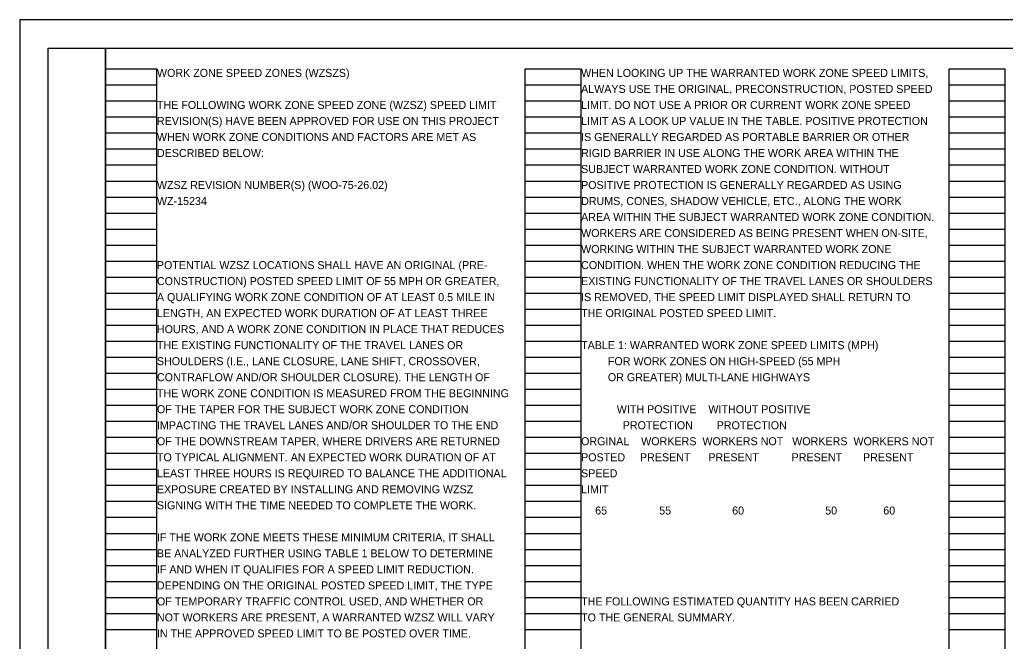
# Model space of a CAD drawing. Extents: x 0 to 34, y 0 to 22.
# Drawn here: x 0 to 17.24, y 11.13 to 22 of the extents above; entities that cross this region are included whole.
import ezdxf

# ---------------------------------------------------------------- set-up
doc = ezdxf.new("R2010")
doc.units = 0
for name, color, linetype in [('SH_Border', 7, 'Continuous'), ('SH_Cut_Line', 7, 'Continuous'), ('SH_Data', 7, 'Continuous'), ('SH_Text', 7, 'Continuous')]:
    doc.layers.add(name, color=color, linetype=linetype)

msp = doc.modelspace()

# ---------------------------------------------------------------- linework, layer by layer
at = {"layer": 'SH_Border'}
for points in [[(0.5, 21.5), (1.5, 21.5), (1.5, 0.5), (0.5, 0.5)], [(1.5, 21.5), (33.5, 21.5), (33.5, 0.5), (1.5, 0.5)]]:
    msp.add_lwpolyline(points, close=True, dxfattribs=at)
at = {"layer": 'SH_Cut_Line'}
msp.add_lwpolyline([(0, 0), (34, 0), (34, 22), (0, 22)], close=True, dxfattribs=at)
at = {"layer": 'SH_Data'}
for p, q in [((1.5, 0.98), (1.5, 21.14)), ((1.5, 21.14), (2.4, 21.14)), ((2.4, 0.98), (2.4, 21.14)), ((8.84, 0.98), (8.84, 21.14)), ((8.84, 21.14), (9.82, 21.14)), ((9.82, 0.98), (9.82, 21.14)), ((16.26, 0.98), (16.26, 21.14)), ((16.26, 21.14), (17.24, 21.14)), ((17.24, 0.98), (17.24, 21.14)), ((1.5, 20.86), (2.4, 20.86)), ((8.84, 20.86), (9.82, 20.86)), ((16.26, 20.86), (17.24, 20.86)), ((1.5, 20.58), (2.4, 20.58)), ((8.84, 20.58), (9.82, 20.58)), ((16.26, 20.58), (17.24, 20.58)), ((1.5, 20.3), (2.4, 20.3)), ((8.84, 20.3), (9.82, 20.3)), ((16.26, 20.3), (17.24, 20.3)), ((1.5, 20.02), (2.4, 20.02)), ((8.84, 20.02), (9.82, 20.02)), ((16.26, 20.02), (17.24, 20.02)), ((1.5, 19.74), (2.4, 19.74)), ((8.84, 19.74), (9.82, 19.74)), ((16.26, 19.74), (17.24, 19.74)), ((1.5, 19.46), (2.4, 19.46)), ((8.84, 19.46), (9.82, 19.46)), ((16.26, 19.46), (17.24, 19.46)), ((1.5, 19.18), (2.4, 19.18)), ((8.84, 19.18), (9.82, 19.18)), ((16.26, 19.18), (17.24, 19.18)), ((1.5, 18.9), (2.4, 18.9)), ((8.84, 18.9), (9.82, 18.9)), ((16.26, 18.9), (17.24, 18.9)), ((1.5, 18.62), (2.4, 18.62)), ((8.84, 18.62), (9.82, 18.62)), ((16.26, 18.62), (17.24, 18.62)), ((1.5, 18.34), (2.4, 18.34)), ((8.84, 18.34), (9.82, 18.34)), ((16.26, 18.34), (17.24, 18.34)), ((1.5, 18.06), (2.4, 18.06)), ((8.84, 18.06), (9.82, 18.06)), ((16.26, 18.06), (17.24, 18.06)), ((1.5, 17.78), (2.4, 17.78)), ((8.84, 17.78), (9.82, 17.78)), ((16.26, 17.78), (17.24, 17.78)), ((1.5, 17.5), (2.4, 17.5)), ((8.84, 17.5), (9.82, 17.5)), ((16.26, 17.5), (17.24, 17.5)), ((1.5, 17.22), (2.4, 17.22)), ((8.84, 17.22), (9.82, 17.22)), ((16.26, 17.22), (17.24, 17.22)), ((1.5, 16.94), (2.4, 16.94)), ((8.84, 16.94), (9.82, 16.94)), ((16.26, 16.94), (17.24, 16.94)), ((1.5, 16.66), (2.4, 16.66)), ((8.84, 16.66), (9.82, 16.66)), ((16.26, 16.66), (17.24, 16.66)), ((1.5, 16.38), (2.4, 16.38)), ((8.84, 16.38), (9.82, 16.38)), ((16.26, 16.38), (17.24, 16.38)), ((1.5, 16.1), (2.4, 16.1)), ((8.84, 16.1), (9.82, 16.1)), ((16.26, 16.1), (17.24, 16.1)), ((1.5, 15.82), (2.4, 15.82)), ((8.84, 15.82), (9.82, 15.82)), ((16.26, 15.82), (17.24, 15.82)), ((1.5, 15.54), (2.4, 15.54)), ((8.84, 15.54), (9.82, 15.54)), ((16.26, 15.54), (17.24, 15.54)), ((1.5, 15.26), (2.4, 15.26)), ((8.84, 15.26), (9.82, 15.26)), ((16.26, 15.26), (17.24, 15.26)), ((1.5, 14.98), (2.4, 14.98)), ((8.84, 14.98), (9.82, 14.98)), ((16.26, 14.98), (17.24, 14.98)), ((1.5, 14.7), (2.4, 14.7)), ((8.84, 14.7), (9.82, 14.7)), ((16.26, 14.7), (17.24, 14.7)), ((1.5, 14.42), (2.4, 14.42)), ((8.84, 14.42), (9.82, 14.42)), ((16.26, 14.42), (17.24, 14.42)), ((1.5, 14.14), (2.4, 14.14)), ((8.84, 14.14), (9.82, 14.14)), ((16.26, 14.14), (17.24, 14.14)), ((1.5, 13.86), (2.4, 13.86)), ((8.84, 13.86), (9.82, 13.86)), ((16.26, 13.86), (17.24, 13.86)), ((1.5, 13.58), (2.4, 13.58)), ((8.84, 13.58), (9.82, 13.58)), ((16.26, 13.58), (17.24, 13.58)), ((1.5, 13.3), (2.4, 13.3)), ((8.84, 13.3), (9.82, 13.3)), ((16.26, 13.3), (17.24, 13.3)), ((1.5, 13.02), (2.4, 13.02)), ((8.84, 13.02), (9.82, 13.02)), ((16.26, 13.02), (17.24, 13.02)), ((1.5, 12.74), (2.4, 12.74)), ((8.84, 12.74), (9.82, 12.74)), ((16.26, 12.74), (17.24, 12.74)), ((1.5, 12.46), (2.4, 12.46)), ((8.84, 12.46), (9.82, 12.46)), ((16.26, 12.46), (17.24, 12.46)), ((1.5, 12.18), (2.4, 12.18)), ((8.84, 12.18), (9.82, 12.18)), ((16.26, 12.18), (17.24, 12.18)), ((1.5, 11.9), (2.4, 11.9)), ((8.84, 11.9), (9.82, 11.9)), ((16.26, 11.9), (17.24, 11.9)), ((1.5, 11.62), (2.4, 11.62)), ((8.84, 11.62), (9.82, 11.62)), ((16.26, 11.62), (17.24, 11.62)), ((1.5, 11.34), (2.4, 11.34)), ((8.84, 11.34), (9.82, 11.34)), ((16.26, 11.34), (17.24, 11.34))]:
    msp.add_line(p, q, dxfattribs=at)

# ---------------------------------------------------------------- texts
at = {"layer": 'SH_Text'}
for s, p in [('WORK ZONE SPEED ZONES (WZSZS)', (2.4, 21)), ('WHEN LOOKING UP THE WARRANTED WORK ZONE SPEED LIMITS,', (9.82, 21)), ('ALWAYS USE THE ORIGINAL, PRECONSTRUCTION, POSTED SPEED', (9.82, 20.72)), ('THE FOLLOWING WORK ZONE SPEED ZONE (WZSZ) SPEED LIMIT', (2.4, 20.44)), ('LIMIT. DO NOT USE A PRIOR OR CURRENT WORK ZONE SPEED', (9.82, 20.44)), ('REVISION(S) HAVE BEEN APPROVED FOR USE ON THIS PROJECT', (2.4, 20.16)), ('LIMIT AS A LOOK UP VALUE IN THE TABLE. POSITIVE PROTECTION', (9.82, 20.16)), ('WHEN WORK ZONE CONDITIONS AND FACTORS ARE MET AS', (2.4, 19.88)), ('IS GENERALLY REGARDED AS PORTABLE BARRIER OR OTHER', (9.82, 19.88)), ('DESCRIBED BELOW:', (2.4, 19.6)), ('RIGID BARRIER IN USE ALONG THE WORK AREA WITHIN THE', (9.82, 19.6)), ('SUBJECT WARRANTED WORK ZONE CONDITION. WITHOUT', (9.82, 19.32)), ('WZSZ REVISION NUMBER(S) (WOO-75-26.02)', (2.4, 19.04)), ('POSITIVE PROTECTION IS GENERALLY REGARDED AS USING', (9.82, 19.04)), ('WZ-15234', (2.4, 18.76)), ('DRUMS, CONES, SHADOW VEHICLE, ETC., ALONG THE WORK', (9.82, 18.76)), ('AREA WITHIN THE SUBJECT WARRANTED WORK ZONE CONDITION.', (9.82, 18.48)), ('WORKERS ARE CONSIDERED AS BEING PRESENT WHEN ON-SITE,', (9.82, 18.2)), ('WORKING WITHIN THE SUBJECT WARRANTED WORK ZONE', (9.82, 17.92)), ('POTENTIAL WZSZ LOCATIONS SHALL HAVE AN ORIGINAL (PRE-', (2.4, 17.64)), ('CONDITION. WHEN THE WORK ZONE CONDITION REDUCING THE', (9.82, 17.64)), ('CONSTRUCTION) POSTED SPEED LIMIT OF 55 MPH OR GREATER,', (2.4, 17.36)), ('EXISTING FUNCTIONALITY OF THE TRAVEL LANES OR SHOULDERS', (9.82, 17.36)), ('A QUALIFYING WORK ZONE CONDITION OF AT LEAST 0.5 MILE IN', (2.4, 17.08)), ('IS REMOVED, THE SPEED LIMIT DISPLAYED SHALL RETURN TO', (9.82, 17.08)), ('LENGTH, AN EXPECTED WORK DURATION OF AT LEAST THREE', (2.4, 16.8)), ('THE ORIGINAL POSTED SPEED LIMIT.', (9.82, 16.8)), ('HOURS, AND A WORK ZONE CONDITION IN PLACE THAT REDUCES', (2.4, 16.52)), ('THE EXISTING FUNCTIONALITY OF THE TRAVEL LANES OR', (2.4, 16.24)), ('TABLE 1: WARRANTED WORK ZONE SPEED LIMITS (MPH)', (9.82, 16.24)), ('SHOULDERS (I.E., LANE CLOSURE, LANE SHIFT, CROSSOVER,', (2.4, 15.96)), ('         FOR WORK ZONES ON HIGH-SPEED (55 MPH', (9.82, 15.96)), ('CONTRAFLOW AND/OR SHOULDER CLOSURE). THE LENGTH OF', (2.4, 15.68)), ('         OR GREATER) MULTI-LANE HIGHWAYS', (9.82, 15.68)), ('THE WORK ZONE CONDITION IS MEASURED FROM THE BEGINNING', (2.4, 15.4)), ('OF THE TAPER FOR THE SUBJECT WORK ZONE CONDITION', (2.4, 15.12)), ('            WITH POSITIVE    WITHOUT POSITIVE', (9.82, 15.12)), ('IMPACTING THE TRAVEL LANES AND/OR SHOULDER TO THE END', (2.4, 14.84)), ('              PROTECTION        PROTECTION', (9.82, 14.84)), ('OF THE DOWNSTREAM TAPER, WHERE DRIVERS ARE RETURNED', (2.4, 14.56)), ('ORGINAL    WORKERS  WORKERS NOT   WORKERS  WORKERS NOT', (9.82, 14.56)), ('TO TYPICAL ALIGNMENT. AN EXPECTED WORK DURATION OF AT', (2.4, 14.28)), ('POSTED     PRESENT      PRESENT           PRESENT       PRESENT', (9.82, 14.28)), ('LEAST THREE HOURS IS REQUIRED TO BALANCE THE ADDITIONAL', (2.4, 14)), ('SPEED', (9.82, 14)), ('EXPOSURE CREATED BY INSTALLING AND REMOVING WZSZ', (2.4, 13.72)), ('LIMIT', (9.82, 13.72)), ('SIGNING WITH THE TIME NEEDED TO COMPLETE THE WORK.', (2.4, 13.44)), (' 65        ', (10.014, 13.349)), (' 55      ', (11.134, 13.349)), ('    60              ', (12.254, 13.349)), ('   50 ', (13.934, 13.349)), (' 60', (15.054, 13.349)), ('IF THE WORK ZONE MEETS THESE MINIMUM CRITERIA, IT SHALL', (2.4, 12.88)), ('BE ANALYZED FURTHER USING TABLE 1 BELOW TO DETERMINE', (2.4, 12.6)), ('IF AND WHEN IT QUALIFIES FOR A SPEED LIMIT REDUCTION.', (2.4, 12.32)), ('DEPENDING ON THE ORIGINAL POSTED SPEED LIMIT, THE TYPE', (2.4, 12.04)), ('OF TEMPORARY TRAFFIC CONTROL USED, AND WHETHER OR', (2.4, 11.76)), ('THE FOLLOWING ESTIMATED QUANTITY HAS BEEN CARRIED', (9.82, 11.76)), ('NOT WORKERS ARE PRESENT, A WARRANTED WZSZ WILL VARY', (2.4, 11.48)), ('TO THE GENERAL SUMMARY.', (9.82, 11.48)), ('IN THE APPROVED SPEED LIMIT TO BE POSTED OVER TIME.', (2.4, 11.2))]:
    msp.add_text(s, height=0.14, dxfattribs=at).set_placement(p)

doc.saveas('drawing.dxf')
